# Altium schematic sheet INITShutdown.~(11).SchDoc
size A4
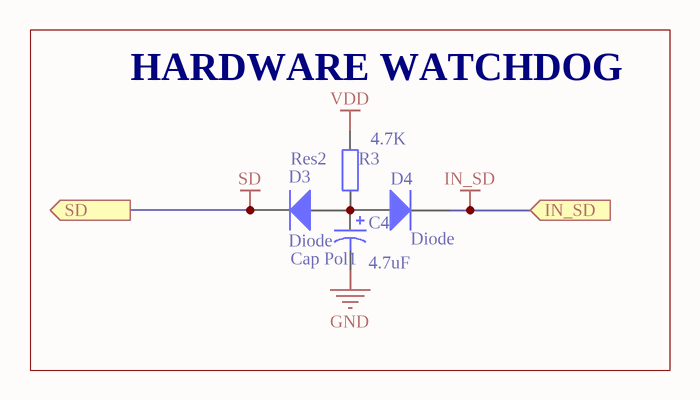
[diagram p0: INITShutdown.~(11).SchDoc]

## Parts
C4  Cap Pol1  value 4.7uF  [CAPPR2.5-6.3X5]
D3  Diode  [DO-204AL]
D4  Diode  [DO-204AL]
R3  Res2  value 4.7K  [AXIAL-0.3]

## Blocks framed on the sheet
HARDWARE WATCHDOG: C4 D3 D4 R3

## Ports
IN_SD (in), SD (out)

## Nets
GND: C4.2
IN_SD: D4.2(K) ; port IN_SD
SD: D3.2(K) ; port SD
VDD: R3.2
NetC4_1: C4.1 D3.1(A) D4.1(A) R3.1

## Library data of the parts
C4 = Cap Pol1: Polarized Capacitor (Radial)
D3 D4 = Diode: Default Diode
R3 = Res2: Resistor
